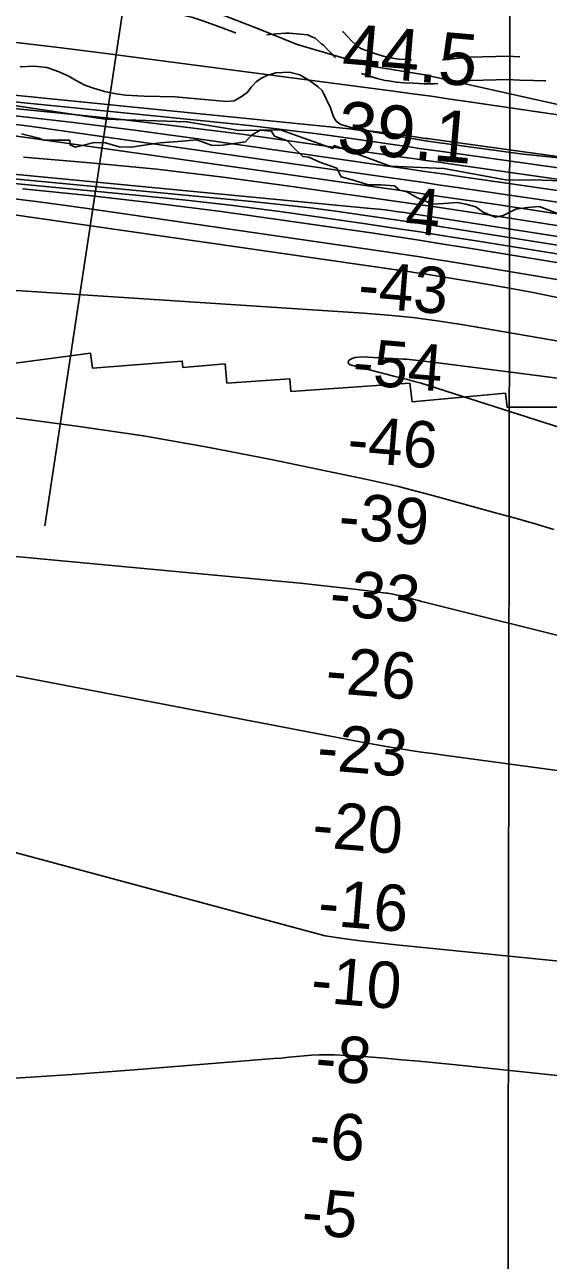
# Model space of a CAD drawing. Extents: x 3219052 to 3256913, y 800770 to 826146.
# Drawn here: x 3233083 to 3233759, y 816241 to 817838 of the extents above; entities that cross this region are included whole.
import ezdxf

# ---------------------------------------------------------------- set-up
doc = ezdxf.new("R2010")
doc.units = 0
for name, color, linetype in [('V-GRID-MAJR', 7, 'Continuous'), ('V-RIVR-EDGE', 7, 'Continuous'), ('V-RIVR-RANG', 7, 'Continuous'), ('V-ROAD-CNTR', 7, 'Continuous'), ('V-RRAP-RVMT', 7, 'Continuous'), ('V-SITE-VEGE', 7, 'Continuous'), ('V-TOPO-DPTH', 7, 'Continuous'), ('V-TOPO-MAJR', 7, 'Continuous'), ('V-TOPO-MINR', 7, 'Continuous'), ('V-TOPO-WATR', 7, 'Continuous')]:
    doc.layers.add(name, color=color, linetype=linetype)

msp = doc.modelspace()

# ---------------------------------------------------------------- linework, layer by layer
at = {"layer": 'V-GRID-MAJR'}
msp.add_spline([(3233694.8, 806171.3), (3233702.7, 812230.4), (3233710.6, 818292.6), (3233718.6, 824354.9), (3233718.6, 824357.9)], degree=3, dxfattribs=at)
at = {"layer": 'V-RIVR-EDGE'}
for points in [[(3233464.2, 817660.1), (3233450.3, 817666.2), (3233442.5, 817667.1), (3233429, 817680.2), (3233422.5, 817687.6), (3233405.6, 817693.7), (3233401.3, 817700.2), (3233396.9, 817700.3), (3233387.3, 817701.1), (3233375.6, 817694.2), (3233368.2, 817686.4), (3233339.1, 817681.7), (3233325.1, 817681.3), (3233305.6, 817688.7), (3233286.5, 817687.1), (3233258.2, 817684.9), (3233220.4, 817679.4), (3233205.2, 817679.9), (3233187.4, 817684.7), (3233173, 817685.2), (3233148.7, 817679.1), (3233141.7, 817682.2), (3233141.3, 817688.3), (3233125.2, 817688.3), (3233107.8, 817688.4), (3233101.3, 817691), (3233079.1, 817696.7)], [(3233773.5, 817592.8), (3233757.9, 817598.9), (3233747.9, 817602.5), (3233732.7, 817601.2), (3233717.5, 817599), (3233701.3, 817590.8), (3233690.9, 817588.7), (3233675.3, 817595.2), (3233665.7, 817602.2), (3233653.1, 817605.7), (3233642.3, 817607.9), (3233624.4, 817606.7), (3233610.5, 817605.8), (3233590.6, 817613.7), (3233576.7, 817621.6), (3233567.1, 817623.8), (3233560.6, 817629.4), (3233543.2, 817630.8), (3233526.7, 817630.8), (3233509.3, 817636.1), (3233492, 817640.9), (3233486.3, 817652.2), (3233464.2, 817660.1)]]:
    msp.add_lwpolyline(points, dxfattribs=at)
at = {"layer": 'V-RIVR-RANG'}
msp.add_line((3233219.9, 817921.5), (3233109.2, 817189.8), dxfattribs=at)
at = {"layer": 'V-ROAD-CNTR'}
for points in [[(3233171.4, 817881), (3233239.1, 817874.7), (3233328.5, 817854.3), (3233385.3, 817832.3), (3233435, 817811.8), (3233530.6, 817784.1), (3233600, 817772.6), (3233839.3, 817719.4), (3233898.8, 817713.3), (3233948.6, 817722.9), (3234001.8, 817725.3), (3234073.1, 817719.6), (3234135.4, 817705.8), (3234232.9, 817685.2), (3234340.8, 817661.8)], [(3233356, 817827), (3233355.4, 817827.1), (3233337, 817833.8), (3233324.2, 817838.6), (3233312.1, 817842.9), (3233300.2, 817846.9), (3233289.4, 817849.4), (3233267.1, 817854.3), (3233260.3, 817855.2)], [(3233484.6, 817794.9), (3233484.1, 817795.3), (3233478.2, 817801.7), (3233473.1, 817806.9), (3233469.6, 817810.6), (3233466.7, 817813), (3233458.2, 817820), (3233454, 817821.9), (3233449.6, 817824), (3233448.4, 817824.3), (3233424.9, 817826.5), (3233420.6, 817826.4), (3233408.1, 817825.6), (3233395.8, 817824.3)], [(3233582.8, 817792.1), (3233575.6, 817792.4), (3233566.4, 817793.2), (3233558.3, 817794.5), (3233554.6, 817795.1), (3233546.3, 817797), (3233535.5, 817800.5), (3233526.7, 817803.5), (3233518.4, 817806.2), (3233513.9, 817808.8), (3233509.8, 817812.2), (3233505.6, 817816.3), (3233499.9, 817822.4), (3233494.8, 817827.7), (3233493.6, 817828.9)], [(3233722.5, 817796), (3233706.5, 817796.8), (3233691.5, 817796.4), (3233656.6, 817795.4), (3233623.9, 817792.1), (3233622.7, 817792)], [(3233616.7, 817761.5), (3233612.2, 817761.1), (3233599.2, 817761), (3233585.2, 817762), (3233573.7, 817762.4), (3233562.8, 817763.4), (3233553.7, 817764.8), (3233548.9, 817765.6), (3233538.3, 817768.1), (3233526, 817772.1), (3233518.3, 817774.7)], [(3233756.5, 817764.9), (3233754.8, 817765), (3233740.8, 817765.3), (3233722.5, 817766), (3233706.1, 817766.8), (3233692.2, 817766.5), (3233658.6, 817765.5), (3233656.5, 817765.3)]]:
    msp.add_lwpolyline(points, dxfattribs=at)
at = {"layer": 'V-RRAP-RVMT'}
for points in [[(3233751.9, 817636.8), (3233704.4, 817637.1), (3233624.6, 817651.9), (3233555.4, 817654.9), (3233482.9, 817681.3), (3233481.2, 817677.5), (3233413.5, 817701.7), (3233360, 817700.7), (3233292.7, 817712.1), (3233187.2, 817715.4), (3233060.7, 817734.3)], [(3234742.8, 817437.3), (3234632.6, 817477.6), (3234631.4, 817475.1), (3234518.8, 817516.2), (3234471.5, 817518.4), (3234448.4, 817530.5), (3234222.8, 817572.1), (3234173.8, 817574.9), (3233988.7, 817613.6), (3233954.4, 817624.3), (3233890.8, 817631.8), (3233751.9, 817636.8)], [(3233051.1, 817397.6), (3233168.1, 817413.2), (3233170.7, 817393.9), (3233286.6, 817402.9), (3233287.5, 817394.6), (3233342, 817399.2), (3233344.4, 817374.4), (3233425.5, 817380.1), (3233427.1, 817363.4), (3233580.8, 817374.2), (3233583.7, 817350), (3233704.3, 817361.6)], [(3233704.3, 817361.6), (3233706.3, 817343.5), (3233843.6, 817343.5), (3233844.6, 817323.9), (3234004.1, 817313.2), (3234003.4, 817291.9), (3234087.1, 817287.8), (3234086.5, 817268.9), (3234222, 817261.5), (3234221.1, 817218.6), (3234354.6, 817213.2), (3234353.1, 817162.1), (3234487.1, 817156), (3234486, 817116.9), (3234619.6, 817111.9), (3234618.4, 817063.7), (3234750.3, 817056.2), (3234749, 817009.8), (3234894.1, 817001.7), (3234894.5, 816974.6), (3234922.9, 816973.5)]]:
    msp.add_lwpolyline(points, dxfattribs=at)
at = {"layer": 'V-SITE-VEGE'}
msp.add_lwpolyline([(3233077.2, 817782.9), (3233095.7, 817784), (3233111.7, 817782.2), (3233124.4, 817778), (3233139.2, 817771.3), (3233148.8, 817765.8), (3233161, 817759.4), (3233172.2, 817755.5), (3233186, 817751.4), (3233201.3, 817748.3), (3233213.2, 817746.7), (3233237.3, 817745.4), (3233277.6, 817744.3), (3233343.7, 817738.2), (3233353.9, 817739.3), (3233364.1, 817745), (3233370.6, 817750), (3233376.2, 817757.1), (3233382.1, 817763.8), (3233388.3, 817768.1), (3233395.9, 817771.7), (3233407.4, 817775.2), (3233425, 817776.2), (3233438.4, 817772.6), (3233450.2, 817766), (3233462.3, 817757.2), (3233467.5, 817752.5), (3233478.3, 817730.2), (3233482.2, 817718.3), (3233485.4, 817712.9), (3233491.7, 817708.6), (3233510.5, 817703), (3233603.5, 817687), (3233726.9, 817670.1), (3233918.7, 817650.4)], dxfattribs=at)
at = {"layer": 'V-TOPO-DPTH'}
for points in [[(3233048.6, 817711.8), (3233092.3, 817705.8), (3233562.1, 817638.8), (3233580.5, 817636.2), (3233599, 817633.5), (3233617.4, 817630.8), (3233635.9, 817628.1), (3233756.7, 817610.5), (3233835.4, 817598.7), (3233914.2, 817586.8), (3233992.9, 817574.4), (3234071.6, 817561.7), (3234562.5, 817481.6), (3234567.6, 817480.7), (3234572.7, 817479.8), (3234577.7, 817478.7), (3234582.8, 817477.7), (3234621.9, 817469.1), (3234646.5, 817463.5), (3234671, 817457.6), (3234695.4, 817451.3), (3234719.7, 817444.6)], [(3233081.5, 817666.5), (3233167.7, 817659.2), (3233253.7, 817650.7), (3233339.6, 817640.5), (3233425.3, 817629.1), (3233588.5, 817605.7), (3233592.5, 817605.1), (3233596.6, 817604.5), (3233600.6, 817603.9), (3233604.6, 817603.3), (3233630.5, 817599.5), (3233647.5, 817596.9), (3233664.5, 817594.4), (3233681.4, 817591.8), (3233698.4, 817589.2), (3233806.4, 817572.5)], [(3233806.4, 817572.5), (3233698.4, 817589.2), (3233681.4, 817591.8), (3233664.5, 817594.4), (3233647.5, 817596.9), (3233630.5, 817599.5), (3233604.6, 817603.3), (3233600.6, 817603.9), (3233596.6, 817604.5), (3233592.5, 817605.1), (3233588.5, 817605.7), (3233425.3, 817629.1), (3233339.6, 817640.5), (3233253.7, 817650.7), (3233167.7, 817659.2), (3233081.5, 817666.5)], [(3234765.9, 817357.4), (3234698, 817375.6), (3234602, 817401), (3234582, 817406.1), (3234562, 817411), (3234541.9, 817415.6), (3234521.7, 817419.9), (3234398.4, 817445.3), (3234316.5, 817461.5), (3234234.4, 817477.1), (3234152.1, 817491.5), (3234069.7, 817505.2), (3233665.5, 817569.4), (3233630, 817575), (3233594.5, 817580.5), (3233559, 817585.9), (3233523.5, 817591.2), (3233487.9, 817596.2), (3233452.3, 817600.8), (3233416.6, 817604.8), (3233380.9, 817608.5), (3232860.5, 817658.3)], [(3234765.9, 817357.4), (3234698, 817375.6), (3234602, 817401), (3234582, 817406.1), (3234562, 817411), (3234541.9, 817415.6), (3234521.7, 817419.9), (3234398.4, 817445.3), (3234316.5, 817461.5), (3234234.4, 817477.1), (3234152.1, 817491.5), (3234069.7, 817505.2), (3233665.5, 817569.4), (3233630, 817575), (3233594.5, 817580.5), (3233559, 817585.9), (3233523.5, 817591.2), (3233487.9, 817596.2), (3233452.3, 817600.8), (3233416.6, 817604.8), (3233380.9, 817608.5), (3232860.5, 817658.3)], [(3233777.2, 817483.8), (3233739.8, 817491.4), (3233702.2, 817498.4), (3233664.6, 817504.9), (3233609.5, 817513.9), (3233599.4, 817515.5), (3233589.2, 817517.1), (3233579.1, 817518.6), (3233568.9, 817520.1), (3232854.2, 817622.7)], [(3232854.2, 817622.7), (3233568.9, 817520.1), (3233579.1, 817518.6), (3233589.2, 817517.1), (3233599.4, 817515.5), (3233609.5, 817513.9), (3233664.6, 817504.9), (3233702.2, 817498.4), (3233739.8, 817491.4), (3233777.2, 817483.8)], [(3233080.3, 817625.5), (3233166, 817616.7), (3233251.5, 817607), (3233337, 817596), (3233422.3, 817584.2), (3233530.6, 817568.4), (3233561.7, 817563.8), (3233592.7, 817559), (3233623.7, 817554.1), (3233654.7, 817549.1), (3233822.9, 817521.6)], [(3233080.3, 817625.5), (3233166, 817616.7), (3233251.5, 817607), (3233337, 817596), (3233422.3, 817584.2), (3233530.6, 817568.4), (3233561.7, 817563.8), (3233592.7, 817559), (3233623.7, 817554.1), (3233654.7, 817549.1), (3233822.9, 817521.6)], [(3233818.1, 817500.2), (3233742.5, 817513.2), (3233632, 817531.4), (3233611.5, 817534.7), (3233591, 817537.9), (3233570.4, 817541.1), (3233549.9, 817544.1), (3233161.4, 817600.4), (3233105, 817608.1), (3233048.6, 817615.3)], [(3233048.6, 817615.3), (3233105, 817608.1), (3233161.4, 817600.4), (3233549.9, 817544.1), (3233570.4, 817541.1), (3233591, 817537.9), (3233611.5, 817534.7), (3233632, 817531.4), (3233742.5, 817513.2), (3233818.1, 817500.2)], [(3232841.4, 817171.9), (3233416.2, 817117.9), (3233439.3, 817115.7), (3233462.4, 817113.3), (3233485.4, 817110.7), (3233508.5, 817108.1), (3233550.1, 817103.1), (3233552.3, 817102.8), (3233556.7, 817102), (3233558.9, 817101.6), (3233569.4, 817099.2), (3233573.2, 817098.4), (3233577, 817097.4), (3233580.7, 817096.4), (3233584.4, 817095.4), (3233588.2, 817094.3), (3233591.9, 817093.3), (3233595.6, 817092.3), (3233599.4, 817091.3), (3233805, 817040.1)], [(3233805, 817040.1), (3233599.4, 817091.3), (3233595.6, 817092.3), (3233591.9, 817093.3), (3233588.2, 817094.3), (3233584.4, 817095.4), (3233580.7, 817096.4), (3233577, 817097.4), (3233573.2, 817098.4), (3233569.4, 817099.2), (3233558.9, 817101.6), (3233556.7, 817102), (3233552.3, 817102.8), (3233550.1, 817103.1), (3233508.5, 817108.1), (3233485.4, 817110.7), (3233462.4, 817113.3), (3233439.3, 817115.7), (3233416.2, 817117.9), (3232841.4, 817171.9)], [(3233023.3, 817005.2), (3233509.5, 816912.1), (3233523.8, 816909.5), (3233538.2, 816906.9), (3233552.5, 816904.4), (3233566.9, 816902.1), (3233581.3, 816899.8), (3233595.7, 816897.6), (3233610.1, 816895.6), (3233624.5, 816893.6), (3234462.3, 816780.3), (3234466.5, 816779.4), (3234473.5, 816777.3), (3234474.7, 816776.9), (3234478.2, 816775.4), (3235120.2, 816495.7)], [(3235120.2, 816495.7), (3234478.2, 816775.4), (3234474.7, 816776.9), (3234473.5, 816777.3), (3234466.5, 816779.4), (3234462.3, 816780.3), (3233624.5, 816893.6), (3233610.1, 816895.6), (3233595.7, 816897.6), (3233581.3, 816899.8), (3233566.9, 816902.1), (3233552.5, 816904.4), (3233538.2, 816906.9), (3233523.8, 816909.5), (3233509.5, 816912.1), (3233023.3, 817005.2)], [(3232852.3, 816826.3), (3233471.1, 816660.2), (3233494, 816656.9), (3233517, 816653.9), (3233540, 816651.2), (3233563.1, 816648.7), (3234070.1, 816597.5), (3234130.1, 816591), (3234189.9, 816583.7), (3234249.7, 816575.5), (3234309.3, 816566.5), (3234362.3, 816558.1), (3234395.3, 816552.3), (3234428.1, 816545.8), (3234460.6, 816538.2), (3234493, 816530), (3234633, 816491.7), (3234734.8, 816463.3)], [(3234734.8, 816463.3), (3234633, 816491.7), (3234493, 816530), (3234460.6, 816538.2), (3234428.1, 816545.8), (3234395.3, 816552.3), (3234362.3, 816558.1), (3234309.3, 816566.5), (3234249.7, 816575.5), (3234189.9, 816583.7), (3234130.1, 816591), (3234070.1, 816597.5), (3233563.1, 816648.7), (3233540, 816651.2), (3233517, 816653.9), (3233494, 816656.9), (3233471.1, 816660.2), (3232852.3, 816826.3)]]:
    msp.add_lwpolyline(points, dxfattribs=at)
at = {"layer": 'V-TOPO-MAJR'}
for points in [[(3234882.6, 817458.2), (3234639.6, 817515.8), (3234610, 817522.5), (3234580.2, 817528.9), (3234550.4, 817534.8), (3234520.5, 817540.4), (3234448.9, 817552.9), (3234383, 817564.2), (3234317.2, 817574.9), (3234251.1, 817585), (3234185.1, 817594.6), (3233622.2, 817673.5), (3233612.4, 817674.9), (3233602.6, 817676.3), (3233592.8, 817677.7), (3233582.9, 817679.1), (3233510.8, 817689.6), (3233464.9, 817695.9), (3233419, 817701.9), (3233372.9, 817707.2), (3233326.9, 817712.1), (3232867.4, 817758)], [(3234965.1, 817179.9), (3234668.5, 817270.1), (3234569.5, 817291.9), (3234557, 817294.5), (3234544.4, 817297.1), (3234531.8, 817299.5), (3234519.1, 817301.7), (3234247.5, 817347.6), (3234137, 817366.4), (3234026.5, 817385.2), (3233916, 817404), (3233805.5, 817422.9), (3233647.5, 817450), (3233616, 817454.8), (3233584.3, 817459.1), (3233552.6, 817462.3), (3233520.8, 817464.9), (3233025.7, 817497.2)], [(3233070, 817329.4), (3233153.3, 817318.5), (3233236.4, 817306.1), (3233319.1, 817291.6), (3233401.6, 817275.6), (3233523.3, 817250.3), (3233544.7, 817245.7), (3233566, 817240.7), (3233587.2, 817235.4), (3233608.4, 817229.8), (3233689.7, 817207.4), (3233715.5, 817200.2), (3233741.2, 817192.8), (3233766.8, 817185.1)]]:
    msp.add_lwpolyline(points, dxfattribs=at)
at = {"layer": 'V-TOPO-MINR'}
for points in [[(3234732.5, 817550.9), (3234696.7, 817559.6), (3234660.8, 817567.9), (3234603.9, 817580.5), (3234596.3, 817582.1), (3234588.7, 817583.7), (3234581.1, 817585.1), (3234573.5, 817586.5), (3234230.4, 817647.3), (3234127, 817665.2), (3234023.5, 817682.4), (3233919.8, 817698.8), (3233816, 817714.6), (3233657.1, 817738), (3233632.7, 817741.5), (3233608.3, 817745), (3233583.9, 817748.3), (3233559.5, 817751.6), (3233184.8, 817800.7), (3233126.8, 817808.1), (3233068.7, 817815.1)], [(3235113.7, 817422.9), (3234644.5, 817535.3), (3234614, 817542.4), (3234583.3, 817549.1), (3234552.6, 817555.2), (3234521.8, 817561), (3234490.9, 817566.3), (3234460, 817571.4), (3234429, 817576.1), (3234398, 817580.6), (3233609.5, 817689.5), (3233606.6, 817689.9), (3233603.8, 817690.3), (3233600.9, 817690.7), (3233598, 817691.1), (3233577.3, 817694.2), (3233564, 817696), (3233550.8, 817697.7), (3233537.5, 817699.3), (3233524.2, 817700.7), (3232876.7, 817765.8)], [(3234753.7, 817470.2), (3234618.7, 817501.8), (3234598.1, 817506.4), (3234577.4, 817510.8), (3234556.7, 817514.8), (3234536, 817518.5), (3234378.3, 817545.7), (3234278.6, 817562.4), (3234178.8, 817578.5), (3234078.9, 817593.8), (3233978.9, 817608.4), (3233635.1, 817657.3), (3233618.2, 817659.7), (3233601.4, 817662.1), (3233584.6, 817664.6), (3233567.7, 817667), (3233442.9, 817685), (3233363.5, 817695.9), (3233284.1, 817706.2), (3233204.6, 817715.3), (3233125, 817723.7), (3232858.1, 817750.2)], [(3233787.8, 817590.7), (3233740.3, 817597.9), (3233692.8, 817605), (3233620.3, 817615.7), (3233609, 817617.4), (3233597.8, 817619), (3233586.5, 817620.7), (3233575.2, 817622.3), (3232875.1, 817721.5)], [(3234742.7, 817456.1), (3234686.9, 817469.3), (3234599.7, 817489.1), (3234587.3, 817491.8), (3234574.9, 817494.3), (3234562.5, 817496.7), (3234550, 817498.9), (3234266.3, 817546.5), (3234155.5, 817564.8), (3234044.6, 817582.5), (3233933.6, 817599.4), (3233822.5, 817615.8), (3233651.4, 817640.5), (3233625.8, 817644.2), (3233600.2, 817647.9), (3233574.6, 817651.6), (3233549, 817655.2), (3233303.9, 817690.4), (3233225.1, 817701.2), (3233146.1, 817711.3), (3233067.1, 817720.3)], [(3234719.7, 817444.6), (3234695.4, 817451.3), (3234671, 817457.6), (3234646.5, 817463.5), (3234621.9, 817469.1), (3234582.8, 817477.7), (3234577.7, 817478.7), (3234572.7, 817479.8), (3234567.6, 817480.7), (3234562.5, 817481.6), (3234071.6, 817561.7), (3233992.9, 817574.4), (3233914.2, 817586.8), (3233835.4, 817598.7), (3233756.7, 817610.5), (3233635.9, 817628.1), (3233617.4, 817630.8), (3233599, 817633.5), (3233580.5, 817636.2), (3233562.1, 817638.8), (3233092.3, 817705.8), (3233048.6, 817711.8)], [(3234726, 817351.4), (3234684.4, 817362.4), (3234642.8, 817373.4), (3234583.3, 817388.9), (3234571.4, 817391.9), (3234559.5, 817394.8), (3234547.5, 817397.5), (3234535.5, 817400.1), (3234350.7, 817438.3), (3234246.1, 817459.2), (3234141.3, 817479.2), (3234036.3, 817497.8), (3233931.2, 817515.5), (3233666.2, 817558.3), (3233629.9, 817564), (3233593.6, 817569.7), (3233557.3, 817575.2), (3233520.9, 817580.7), (3233473, 817587.7), (3233412.7, 817596.1), (3233352.2, 817603.9), (3233291.7, 817610.7), (3233231, 817617), (3232854.3, 817653)], [(3234765.9, 817357.4), (3234698, 817375.6), (3234602, 817401), (3234582, 817406.1), (3234562, 817411), (3234541.9, 817415.6), (3234521.7, 817419.9), (3234398.4, 817445.3), (3234316.5, 817461.5), (3234234.4, 817477.1), (3234152.1, 817491.5), (3234069.7, 817505.2), (3233665.5, 817569.4), (3233630, 817575), (3233594.5, 817580.5), (3233559, 817585.9), (3233523.5, 817591.2), (3233487.9, 817596.2), (3233452.3, 817600.8), (3233416.6, 817604.8), (3233380.9, 817608.5), (3232860.5, 817658.3)], [(3234753.2, 817378.2), (3234621.5, 817413.6), (3234593.1, 817421), (3234564.6, 817428), (3234535.9, 817434.5), (3234507.2, 817440.6), (3234448.7, 817452.6), (3234390.6, 817464), (3234332.4, 817474.9), (3234274, 817485), (3234215.6, 817494.5), (3233617.2, 817588.1), (3233606.4, 817589.8), (3233595.5, 817591.5), (3233584.6, 817593.2), (3233573.7, 817594.8), (3233562.8, 817596.3), (3233551.8, 817597.7), (3233540.9, 817599), (3233529.9, 817600.1), (3232866.8, 817663.6)], [(3233777.2, 817483.8), (3233739.8, 817491.4), (3233702.2, 817498.4), (3233664.6, 817504.9), (3233609.5, 817513.9), (3233599.4, 817515.5), (3233589.2, 817517.1), (3233579.1, 817518.6), (3233568.9, 817520.1), (3232854.2, 817622.7)], [(3233822.9, 817521.6), (3233654.7, 817549.1), (3233623.7, 817554.1), (3233592.7, 817559), (3233561.7, 817563.8), (3233530.6, 817568.4), (3233422.3, 817584.2), (3233337, 817596), (3233251.5, 817607), (3233166, 817616.7), (3233080.3, 817625.5)], [(3233818.1, 817500.2), (3233742.5, 817513.2), (3233632, 817531.4), (3233611.5, 817534.7), (3233591, 817537.9), (3233570.4, 817541.1), (3233549.9, 817544.1), (3233161.4, 817600.4), (3233105, 817608.1), (3233048.6, 817615.3)], [(3234532.4, 817282.8), (3233701.2, 817389.7), (3233681, 817392.3), (3233660.8, 817394.8), (3233640.6, 817397.4), (3233620.3, 817400), (3233587.8, 817404), (3233583.8, 817404.5), (3233579.9, 817404.9), (3233575.9, 817405.2), (3233571.9, 817405.5), (3233518.1, 817408.3), (3233514.1, 817408.1), (3233510.1, 817407.5), (3233506.3, 817406.2), (3233502.7, 817404.4), (3233501.4, 817402.6), (3233501, 817401), (3233501.9, 817399.5), (3233503.6, 817398.1), (3233560.1, 817383.5), (3233568.9, 817381.2), (3233577.7, 817379), (3233586.5, 817376.7), (3233595.3, 817374.5), (3234154, 817195.5)], [(3232841.4, 817171.9), (3233416.2, 817117.9), (3233439.3, 817115.7), (3233462.4, 817113.3), (3233485.4, 817110.7), (3233508.5, 817108.1), (3233550.1, 817103.1), (3233552.3, 817102.8), (3233556.7, 817102), (3233558.9, 817101.6), (3233569.4, 817099.2), (3233573.2, 817098.4), (3233577, 817097.4), (3233580.7, 817096.4), (3233584.4, 817095.4), (3233588.2, 817094.3), (3233591.9, 817093.3), (3233595.6, 817092.3), (3233599.4, 817091.3), (3233805, 817040.1)], [(3233023.3, 817005.2), (3233509.5, 816912.1), (3233523.8, 816909.5), (3233538.2, 816906.9), (3233552.5, 816904.4), (3233566.9, 816902.1), (3233581.3, 816899.8), (3233595.7, 816897.6), (3233610.1, 816895.6), (3233624.5, 816893.6), (3234462.3, 816780.3), (3234466.5, 816779.4), (3234473.5, 816777.3), (3234474.7, 816776.9), (3234478.2, 816775.4), (3235120.2, 816495.7)], [(3232852.3, 816826.3), (3233471.1, 816660.2), (3233494, 816656.9), (3233517, 816653.9), (3233540, 816651.2), (3233563.1, 816648.7), (3234070.1, 816597.5), (3234130.1, 816591), (3234189.9, 816583.7), (3234249.7, 816575.5), (3234309.3, 816566.5), (3234362.3, 816558.1), (3234395.3, 816552.3), (3234428.1, 816545.8), (3234460.6, 816538.2), (3234493, 816530), (3234633, 816491.7), (3234734.8, 816463.3)], [(3233064.1, 816475.7), (3233144.4, 816480.9), (3233224.7, 816486.8), (3233404.9, 816501.5), (3233414.7, 816502.3), (3233424.5, 816503.2), (3233434.3, 816504.1), (3233444.1, 816505.1), (3233453.8, 816505.9), (3233463.6, 816506.4), (3233473.5, 816506.5), (3233483.3, 816506.3), (3233499.3, 816505.7), (3233501.9, 816505.6), (3233504.5, 816505.4), (3233507.2, 816505.3), (3233509.8, 816505.1), (3233548.4, 816501.9), (3233570.3, 816500.1), (3233592.2, 816498.1), (3233614.1, 816496), (3233636, 816493.8), (3234377.4, 816415.8)]]:
    msp.add_lwpolyline(points, dxfattribs=at)
at = {"layer": 'V-TOPO-WATR'}
msp.add_lwpolyline([(3233806.4, 817572.5), (3233698.4, 817589.2), (3233681.4, 817591.8), (3233664.5, 817594.4), (3233647.5, 817596.9), (3233630.5, 817599.5), (3233604.6, 817603.3), (3233600.6, 817603.9), (3233596.6, 817604.5), (3233592.5, 817605.1), (3233588.5, 817605.7), (3233425.3, 817629.1), (3233339.6, 817640.5), (3233253.7, 817650.7), (3233167.7, 817659.2), (3233081.5, 817666.5)], dxfattribs=at)

# ---------------------------------------------------------------- texts
at = {"layer": 'V-RIVR-RANG'}
for s, height, rotation, p in [('44.5', 67, 355.0683, (3233491.4, 817772.5)), ('39.1', 67, 355.0683, (3233485.5, 817672.7)), ('4', 60, 355.2909, (3233573.2, 817568.1)), ('-43', 60, 355.2909, (3233512.3, 817472.8)), ('-54', 60, 355.2909, (3233505.2, 817373.1)), ('-46', 60, 355.2909, (3233498.5, 817273.3)), ('-39', 60, 355.2909, (3233487.1, 817173.9)), ('-33', 60, 355.2909, (3233475.7, 817074.5)), ('-26', 60, 355.2909, (3233470.6, 816974.6)), ('-23', 60, 355.2909, (3233459.4, 816875.1)), ('-20', 60, 355.2909, (3233453.2, 816775.3)), ('-16', 60, 355.2909, (3233460.6, 816674.4)), ('-10', 60, 355.2909, (3233451.6, 816574.8)), ('-8', 60, 355.2909, (3233457.1, 816474)), ('-6', 60, 355.2909, (3233449.3, 816374.3)), ('-5', 60, 355.2909, (3233439.5, 816274.8))]:
    msp.add_text(s, height=height, rotation=rotation, dxfattribs=at).set_placement(p)

doc.saveas('drawing.dxf')
